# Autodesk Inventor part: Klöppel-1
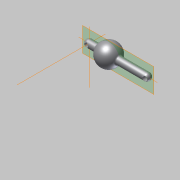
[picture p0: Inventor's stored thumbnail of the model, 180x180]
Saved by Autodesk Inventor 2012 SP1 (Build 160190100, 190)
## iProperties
Created: 2012-03
Part Number: Klöppel-1
Document SubType Name: Modeling
Designer: Kuehlem
Density: 1 g/cm^3
Material: Standard
Author: Kuehlem
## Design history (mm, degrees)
sketch "Skizze1"
  geometry: L1 (-48.556, 0)-(206.841, 0) reference; L2 (0, -6)-(0, 36) reference; L3 (25, 10)-(0, 10); L4 (81.569, 10)-(104.433, 10); L5 (104.433, 10)-(158.284, 10); A1 r 30 centre (53.284, 0) between (81.569, 10) and (25, 10); A2 r 10 centre (158.284, 0) between (168.284, 0) and (158.284, 10); A3 r 10 centre (0, 0) between (0, 10) and (-10, 0); 2 further points
  constraints: 6 end point, 6 point on circle, 5 point on line, 3 centre point, 2 coincident, 1 collinear
  dimensions: "d9" = 10 distance of L5.end point (158.284, 0); "d10" = 10 distance from line of L1 L4.start; "d11" = 10 distance between parallel lines of L1 L3; "d12" = 105 distance of point (158.284, 0) A1.centre; "d13" = 30 radius of A1; "d14" = 25 distance of L3.start L3.end; "d16" = 10 radius of A3 (derived)
revolve "Umdrehung1" sketch "Skizze1" stored, may be unused: angle "d0" = 90 deg
workplane "Arbeitsebene1"
sketch "Skizze3"
  geometry: 4 further points
  constraints: 2 coincident
  dimensions: "d26" = 160 distance of point (0, 0) point (-160, 0)
hole "Hole2" sketch "Skizze3" at (-160, 0), (0, 0) diameter "d18" = 12; stored, may be unused: countersink angle "d22" = 90 deg, drill point angle "d24" = 118 deg; dims "d19" = 6, "d20" = 4, "d21" = 2, "d23" = 8
fillet "Rundung1" dims "d25" = 5
workplane "Arbeitsebene2"
workaxis "Arbeitsachse1"
node "Volumenkörper1"
